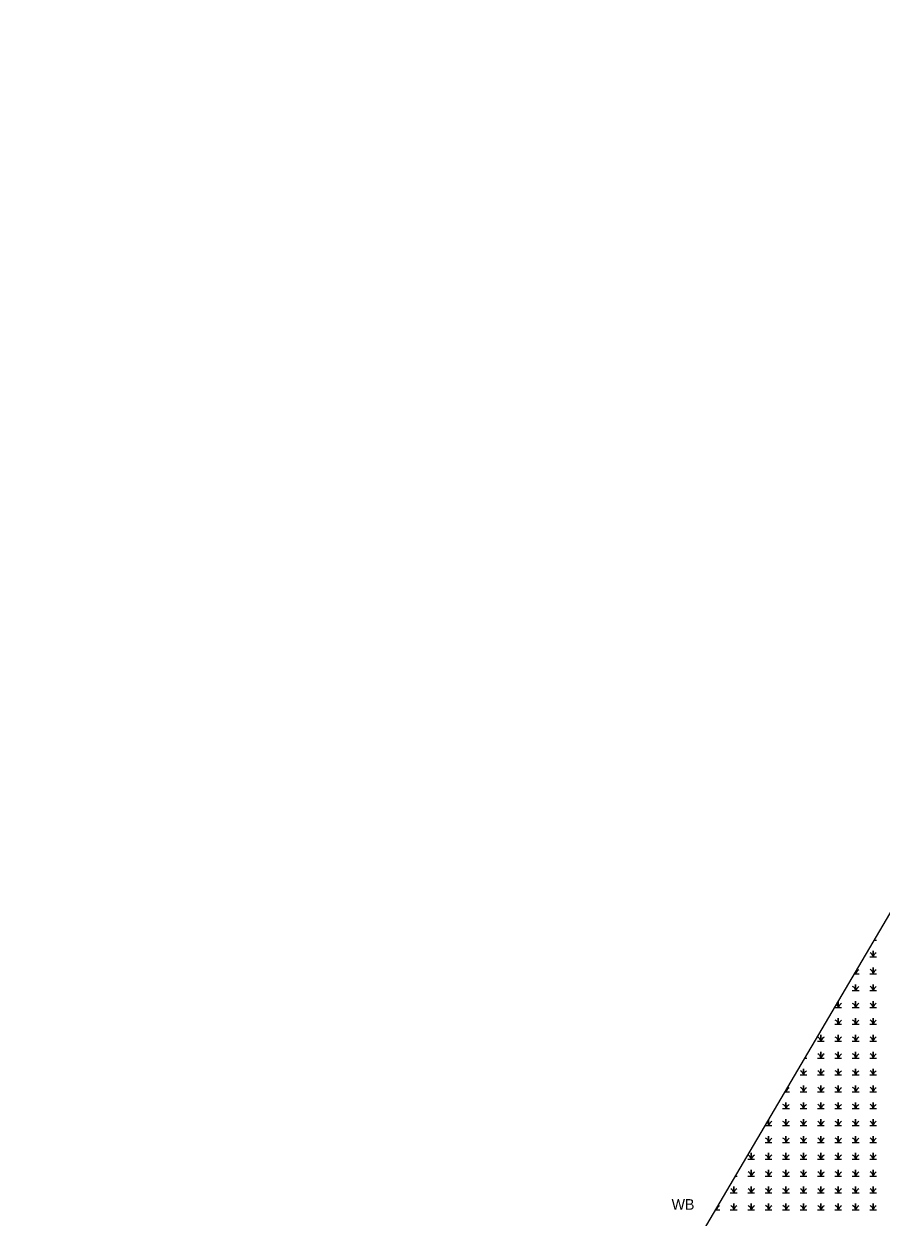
# Model space of a CAD drawing. Extents: x 2379288 to 2381905, y 330670 to 333511.
# Drawn here: x 2379288 to 2380098, y 331977 to 333104 of the extents above; entities that cross this region are included whole.
import ezdxf

# ---------------------------------------------------------------- set-up
doc = ezdxf.new("R2010")
doc.units = 0
for name, color, linetype in [('Default', 7, 'Continuous'), ('Exist Environmental Wetland Boundary Text', 7, 'Continuous'), ('Exist Hydro Swamp or Marsh', 7, 'Continuous')]:
    doc.layers.add(name, color=color, linetype=linetype)

msp = doc.modelspace()

# ---------------------------------------------------------------- linework, layer by layer
at = {"layer": 'Default'}
msp.add_lwpolyline([(2379288.1, 330873.4), (2380109.3, 332268.6), (2380147.9, 332331.8), (2380190.7, 332397.5), (2380235.6, 332461.8), (2380282.6, 332524.7), (2380331.5, 332586), (2380382.3, 332645.8), (2380434.9, 332703.9), (2380489.4, 332760.3), (2380545.6, 332815), (2380603.5, 332867.9), (2380663.1, 332919), (2380724.2, 332968.1), (2380786.8, 333015.3), (2380851, 333060.5), (2380916.5, 333103.7)], dxfattribs=at)
at = {"layer": 'Exist Hydro Swamp or Marsh'}
for p, q in [((2380091.8, 332238.4), (2380093.5, 332238.4)), ((2380026, 332127), (2380027.7, 332127)), ((2379960.4, 332015.6), (2379961.9, 332015.6))]:
    msp.add_line(p, q, dxfattribs=at)
for points in [[(2380087.1, 332222.5), (2380090.3, 332222.5), (2380090.3, 332228.4), (2380090.3, 332222.5), (2380093.5, 332222.5)], [(2380072.9, 332206.6), (2380073.8, 332206.6), (2380073.8, 332208.1)], [(2380073.8, 332208.1), (2380073.8, 332206.6), (2380077.1, 332206.6)], [(2380087.1, 332206.6), (2380090.3, 332206.6), (2380090.3, 332212.5), (2380090.3, 332206.6), (2380093.5, 332206.6)], [(2380070.6, 332190.7), (2380073.8, 332190.7), (2380073.8, 332196.6), (2380073.8, 332190.7), (2380077.1, 332190.7)], [(2380087.1, 332190.7), (2380090.3, 332190.7), (2380090.3, 332196.6), (2380090.3, 332190.7), (2380093.5, 332190.7)], [(2380054.2, 332174.8), (2380057.4, 332174.8), (2380057.4, 332180.4)], [(2380057.4, 332180.4), (2380057.4, 332174.8), (2380060.6, 332174.8)], [(2380070.6, 332174.8), (2380073.8, 332174.8), (2380073.8, 332180.7), (2380073.8, 332174.8), (2380077.1, 332174.8)], [(2380087.1, 332174.8), (2380090.3, 332174.8), (2380090.3, 332180.7), (2380090.3, 332174.8), (2380093.5, 332174.8)], [(2380054.2, 332158.9), (2380057.4, 332158.9), (2380057.4, 332164.8), (2380057.4, 332158.9), (2380060.6, 332158.9)], [(2380070.6, 332158.9), (2380073.8, 332158.9), (2380073.8, 332164.8), (2380073.8, 332158.9), (2380077.1, 332158.9)], [(2380087.1, 332158.9), (2380090.3, 332158.9), (2380090.3, 332164.8), (2380090.3, 332158.9), (2380093.5, 332158.9)], [(2380037.7, 332142.9), (2380040.9, 332142.9), (2380040.9, 332148.9), (2380040.9, 332142.9), (2380044.2, 332142.9)], [(2380054.2, 332142.9), (2380057.4, 332142.9), (2380057.4, 332148.9), (2380057.4, 332142.9), (2380060.6, 332142.9)], [(2380070.6, 332142.9), (2380073.8, 332142.9), (2380073.8, 332148.9), (2380073.8, 332142.9), (2380077.1, 332142.9)], [(2380087.1, 332142.9), (2380090.3, 332142.9), (2380090.3, 332148.9), (2380090.3, 332142.9), (2380093.5, 332142.9)], [(2380037.7, 332127), (2380040.9, 332127), (2380040.9, 332132.9), (2380040.9, 332127), (2380044.2, 332127)], [(2380054.2, 332127), (2380057.4, 332127), (2380057.4, 332132.9), (2380057.4, 332127), (2380060.6, 332127)], [(2380070.6, 332127), (2380073.8, 332127), (2380073.8, 332132.9), (2380073.8, 332127), (2380077.1, 332127)], [(2380087.1, 332127), (2380090.3, 332127), (2380090.3, 332132.9), (2380090.3, 332127), (2380093.5, 332127)], [(2380021.3, 332111.1), (2380024.5, 332111.1), (2380024.5, 332117), (2380024.5, 332111.1), (2380027.7, 332111.1)], [(2380037.7, 332111.1), (2380040.9, 332111.1), (2380040.9, 332117), (2380040.9, 332111.1), (2380044.2, 332111.1)], [(2380054.2, 332111.1), (2380057.4, 332111.1), (2380057.4, 332117), (2380057.4, 332111.1), (2380060.6, 332111.1)], [(2380070.6, 332111.1), (2380073.8, 332111.1), (2380073.8, 332117), (2380073.8, 332111.1), (2380077.1, 332111.1)], [(2380087.1, 332111.1), (2380090.3, 332111.1), (2380090.3, 332117), (2380090.3, 332111.1), (2380093.5, 332111.1)], [(2380007.2, 332095.2), (2380008, 332095.2), (2380008, 332096.5)], [(2380008, 332096.5), (2380008, 332095.2), (2380011.3, 332095.2)], [(2380021.3, 332095.2), (2380024.5, 332095.2), (2380024.5, 332101.1), (2380024.5, 332095.2), (2380027.7, 332095.2)], [(2380037.7, 332095.2), (2380040.9, 332095.2), (2380040.9, 332101.1), (2380040.9, 332095.2), (2380044.2, 332095.2)], [(2380054.2, 332095.2), (2380057.4, 332095.2), (2380057.4, 332101.1), (2380057.4, 332095.2), (2380060.6, 332095.2)], [(2380070.6, 332095.2), (2380073.8, 332095.2), (2380073.8, 332101.1), (2380073.8, 332095.2), (2380077.1, 332095.2)], [(2380087.1, 332095.2), (2380090.3, 332095.2), (2380090.3, 332101.1), (2380090.3, 332095.2), (2380093.5, 332095.2)], [(2380004.8, 332079.3), (2380008, 332079.3), (2380008, 332085.2), (2380008, 332079.3), (2380011.3, 332079.3)], [(2380021.3, 332079.3), (2380024.5, 332079.3), (2380024.5, 332085.2), (2380024.5, 332079.3), (2380027.7, 332079.3)], [(2380037.7, 332079.3), (2380040.9, 332079.3), (2380040.9, 332085.2), (2380040.9, 332079.3), (2380044.2, 332079.3)], [(2380054.2, 332079.3), (2380057.4, 332079.3), (2380057.4, 332085.2), (2380057.4, 332079.3), (2380060.6, 332079.3)], [(2380070.6, 332079.3), (2380073.8, 332079.3), (2380073.8, 332085.2), (2380073.8, 332079.3), (2380077.1, 332079.3)], [(2380087.1, 332079.3), (2380090.3, 332079.3), (2380090.3, 332085.2), (2380090.3, 332079.3), (2380093.5, 332079.3)], [(2380004.8, 332063.4), (2380008, 332063.4), (2380008, 332069.3), (2380008, 332063.4), (2380011.3, 332063.4)], [(2380021.3, 332063.4), (2380024.5, 332063.4), (2380024.5, 332069.3), (2380024.5, 332063.4), (2380027.7, 332063.4)], [(2380037.7, 332063.4), (2380040.9, 332063.4), (2380040.9, 332069.3), (2380040.9, 332063.4), (2380044.2, 332063.4)], [(2380054.2, 332063.4), (2380057.4, 332063.4), (2380057.4, 332069.3), (2380057.4, 332063.4), (2380060.6, 332063.4)], [(2380070.6, 332063.4), (2380073.8, 332063.4), (2380073.8, 332069.3), (2380073.8, 332063.4), (2380077.1, 332063.4)], [(2380087.1, 332063.4), (2380090.3, 332063.4), (2380090.3, 332069.3), (2380090.3, 332063.4), (2380093.5, 332063.4)], [(2379988.5, 332063.4), (2379991.6, 332063.4), (2379991.6, 332068.6)], [(2379991.6, 332068.6), (2379991.6, 332063.4), (2379994.8, 332063.4)], [(2379988.3, 332047.4), (2379991.6, 332047.4), (2379991.6, 332053.4), (2379991.6, 332047.4), (2379994.8, 332047.4)], [(2380004.8, 332047.4), (2380008, 332047.4), (2380008, 332053.4), (2380008, 332047.4), (2380011.3, 332047.4)], [(2380021.3, 332047.4), (2380024.5, 332047.4), (2380024.5, 332053.4), (2380024.5, 332047.4), (2380027.7, 332047.4)], [(2380037.7, 332047.4), (2380040.9, 332047.4), (2380040.9, 332053.4), (2380040.9, 332047.4), (2380044.2, 332047.4)], [(2380054.2, 332047.4), (2380057.4, 332047.4), (2380057.4, 332053.4), (2380057.4, 332047.4), (2380060.6, 332047.4)], [(2380070.6, 332047.4), (2380073.8, 332047.4), (2380073.8, 332053.4), (2380073.8, 332047.4), (2380077.1, 332047.4)], [(2380087.1, 332047.4), (2380090.3, 332047.4), (2380090.3, 332053.4), (2380090.3, 332047.4), (2380093.5, 332047.4)], [(2379971.9, 332031.5), (2379975.1, 332031.5), (2379975.1, 332037.4), (2379975.1, 332031.5), (2379978.3, 332031.5)], [(2379988.3, 332031.5), (2379991.6, 332031.5), (2379991.6, 332037.4), (2379991.6, 332031.5), (2379994.8, 332031.5)], [(2380004.8, 332031.5), (2380008, 332031.5), (2380008, 332037.4), (2380008, 332031.5), (2380011.3, 332031.5)], [(2380021.3, 332031.5), (2380024.5, 332031.5), (2380024.5, 332037.4), (2380024.5, 332031.5), (2380027.7, 332031.5)], [(2380037.7, 332031.5), (2380040.9, 332031.5), (2380040.9, 332037.4), (2380040.9, 332031.5), (2380044.2, 332031.5)], [(2380054.2, 332031.5), (2380057.4, 332031.5), (2380057.4, 332037.4), (2380057.4, 332031.5), (2380060.6, 332031.5)], [(2380070.6, 332031.5), (2380073.8, 332031.5), (2380073.8, 332037.4), (2380073.8, 332031.5), (2380077.1, 332031.5)], [(2380087.1, 332031.5), (2380090.3, 332031.5), (2380090.3, 332037.4), (2380090.3, 332031.5), (2380093.5, 332031.5)], [(2379971.9, 332015.6), (2379975.1, 332015.6), (2379975.1, 332021.5), (2379975.1, 332015.6), (2379978.3, 332015.6)], [(2379988.3, 332015.6), (2379991.6, 332015.6), (2379991.6, 332021.5), (2379991.6, 332015.6), (2379994.8, 332015.6)], [(2380004.8, 332015.6), (2380008, 332015.6), (2380008, 332021.5), (2380008, 332015.6), (2380011.3, 332015.6)], [(2380021.3, 332015.6), (2380024.5, 332015.6), (2380024.5, 332021.5), (2380024.5, 332015.6), (2380027.7, 332015.6)], [(2380037.7, 332015.6), (2380040.9, 332015.6), (2380040.9, 332021.5), (2380040.9, 332015.6), (2380044.2, 332015.6)], [(2380054.2, 332015.6), (2380057.4, 332015.6), (2380057.4, 332021.5), (2380057.4, 332015.6), (2380060.6, 332015.6)], [(2380070.6, 332015.6), (2380073.8, 332015.6), (2380073.8, 332021.5), (2380073.8, 332015.6), (2380077.1, 332015.6)], [(2380087.1, 332015.6), (2380090.3, 332015.6), (2380090.3, 332021.5), (2380090.3, 332015.6), (2380093.5, 332015.6)], [(2379955.4, 331999.7), (2379958.7, 331999.7), (2379958.7, 332005.6), (2379958.7, 331999.7), (2379961.9, 331999.7)], [(2379971.9, 331999.7), (2379975.1, 331999.7), (2379975.1, 332005.6), (2379975.1, 331999.7), (2379978.3, 331999.7)], [(2379988.3, 331999.7), (2379991.6, 331999.7), (2379991.6, 332005.6), (2379991.6, 331999.7), (2379994.8, 331999.7)], [(2380004.8, 331999.7), (2380008, 331999.7), (2380008, 332005.6), (2380008, 331999.7), (2380011.3, 331999.7)], [(2380021.3, 331999.7), (2380024.5, 331999.7), (2380024.5, 332005.6), (2380024.5, 331999.7), (2380027.7, 331999.7)], [(2380037.7, 331999.7), (2380040.9, 331999.7), (2380040.9, 332005.6), (2380040.9, 331999.7), (2380044.2, 331999.7)], [(2380054.2, 331999.7), (2380057.4, 331999.7), (2380057.4, 332005.6), (2380057.4, 331999.7), (2380060.6, 331999.7)], [(2380070.6, 331999.7), (2380073.8, 331999.7), (2380073.8, 332005.6), (2380073.8, 331999.7), (2380077.1, 331999.7)], [(2380087.1, 331999.7), (2380090.3, 331999.7), (2380090.3, 332005.6), (2380090.3, 331999.7), (2380093.5, 331999.7)], [(2379941.7, 331983.8), (2379942.2, 331983.8), (2379942.2, 331984.7)], [(2379942.2, 331984.7), (2379942.2, 331983.8), (2379945.4, 331983.8)], [(2379955.4, 331983.8), (2379958.7, 331983.8), (2379958.7, 331989.7), (2379958.7, 331983.8), (2379961.9, 331983.8)], [(2379971.9, 331983.8), (2379975.1, 331983.8), (2379975.1, 331989.7), (2379975.1, 331983.8), (2379978.3, 331983.8)], [(2379988.3, 331983.8), (2379991.6, 331983.8), (2379991.6, 331989.7), (2379991.6, 331983.8), (2379994.8, 331983.8)], [(2380004.8, 331983.8), (2380008, 331983.8), (2380008, 331989.7), (2380008, 331983.8), (2380011.3, 331983.8)], [(2380021.3, 331983.8), (2380024.5, 331983.8), (2380024.5, 331989.7), (2380024.5, 331983.8), (2380027.7, 331983.8)], [(2380037.7, 331983.8), (2380040.9, 331983.8), (2380040.9, 331989.7), (2380040.9, 331983.8), (2380044.2, 331983.8)], [(2380054.2, 331983.8), (2380057.4, 331983.8), (2380057.4, 331989.7), (2380057.4, 331983.8), (2380060.6, 331983.8)], [(2380070.6, 331983.8), (2380073.8, 331983.8), (2380073.8, 331989.7), (2380073.8, 331983.8), (2380077.1, 331983.8)], [(2380087.1, 331983.8), (2380090.3, 331983.8), (2380090.3, 331989.7), (2380090.3, 331983.8), (2380093.5, 331983.8)]]:
    msp.add_lwpolyline(points, dxfattribs=at)
for centre, radius, start, end in [((2380085.7, 332222.2), 4.61, 4.1403, 67.535), ((2380097.1, 332220.3), 7.21, 122.1274, 161.6222), ((2380069.2, 332206.3), 4.61, 4.1403, 18.2723), ((2380080.7, 332204.3), 7.21, 122.1274, 161.6222), ((2380085.7, 332206.3), 4.61, 4.1403, 67.535), ((2380097.1, 332204.3), 7.21, 122.1274, 161.6222), ((2380069.2, 332190.4), 4.61, 4.1403, 67.535), ((2380080.7, 332188.4), 7.21, 122.1274, 161.6222), ((2380085.7, 332190.4), 4.61, 4.1403, 67.535), ((2380097.1, 332188.4), 7.21, 122.1274, 161.6222), ((2380052.8, 332174.4), 4.61, 4.1403, 47.5604), ((2380064.2, 332172.5), 7.21, 122.1274, 161.6222), ((2380069.2, 332174.4), 4.61, 4.1403, 67.535), ((2380080.7, 332172.5), 7.21, 122.1274, 161.6222), ((2380085.7, 332174.4), 4.61, 4.1403, 67.535), ((2380097.1, 332172.5), 7.21, 122.1274, 161.6222), ((2380052.8, 332158.5), 4.61, 4.1403, 67.535), ((2380064.2, 332156.6), 7.21, 122.1274, 161.6222), ((2380069.2, 332158.5), 4.61, 4.1403, 67.535), ((2380080.7, 332156.6), 7.21, 122.1274, 161.6222), ((2380085.7, 332158.5), 4.61, 4.1403, 67.535), ((2380097.1, 332156.6), 7.21, 122.1274, 161.6222), ((2380036.3, 332142.6), 4.61, 4.1403, 67.535), ((2380047.8, 332140.7), 7.21, 122.1274, 161.6222), ((2380052.8, 332142.6), 4.61, 4.1403, 67.535), ((2380064.2, 332140.7), 7.21, 122.1274, 161.6222), ((2380069.2, 332142.6), 4.61, 4.1403, 67.535), ((2380080.7, 332140.7), 7.21, 122.1274, 161.6222), ((2380085.7, 332142.6), 4.61, 4.1403, 67.535), ((2380097.1, 332140.7), 7.21, 122.1274, 161.6222), ((2380036.3, 332126.7), 4.61, 4.1403, 67.535), ((2380047.8, 332124.8), 7.21, 122.1274, 161.6222), ((2380052.8, 332126.7), 4.61, 4.1403, 67.535), ((2380064.2, 332124.8), 7.21, 122.1274, 161.6222), ((2380069.2, 332126.7), 4.61, 4.1403, 67.535), ((2380080.7, 332124.8), 7.21, 122.1274, 161.6222), ((2380085.7, 332126.7), 4.61, 4.1403, 67.535), ((2380097.1, 332124.8), 7.21, 122.1274, 161.6222), ((2380019.9, 332110.8), 4.61, 4.1403, 67.535), ((2380031.3, 332108.8), 7.21, 122.1274, 161.6222), ((2380036.3, 332110.8), 4.61, 4.1403, 67.535), ((2380047.8, 332108.8), 7.21, 122.1274, 161.6222), ((2380052.8, 332110.8), 4.61, 4.1403, 67.535), ((2380064.2, 332108.8), 7.21, 122.1274, 161.6222), ((2380069.2, 332110.8), 4.61, 4.1403, 67.535), ((2380080.7, 332108.8), 7.21, 122.1274, 161.6222), ((2380085.7, 332110.8), 4.61, 4.1403, 67.535), ((2380097.1, 332108.8), 7.21, 122.1274, 161.6222), ((2380003.4, 332094.9), 4.61, 4.1403, 17.0082), ((2380014.9, 332092.9), 7.21, 122.1274, 161.6222), ((2380019.9, 332094.9), 4.61, 4.1403, 67.535), ((2380031.3, 332092.9), 7.21, 122.1274, 161.6222), ((2380036.3, 332094.9), 4.61, 4.1403, 67.535), ((2380047.8, 332092.9), 7.21, 122.1274, 161.6222), ((2380052.8, 332094.9), 4.61, 4.1403, 67.535), ((2380064.2, 332092.9), 7.21, 122.1274, 161.6222), ((2380069.2, 332094.9), 4.61, 4.1403, 67.535), ((2380080.7, 332092.9), 7.21, 122.1274, 161.6222), ((2380085.7, 332094.9), 4.61, 4.1403, 67.535), ((2380097.1, 332092.9), 7.21, 122.1274, 161.6222), ((2380003.4, 332078.9), 4.61, 4.1403, 67.535), ((2380014.9, 332077), 7.21, 122.1274, 161.6222), ((2380019.9, 332078.9), 4.61, 4.1403, 67.535), ((2380031.3, 332077), 7.21, 122.1274, 161.6222), ((2380036.3, 332078.9), 4.61, 4.1403, 67.535), ((2380047.8, 332077), 7.21, 122.1274, 161.6222), ((2380052.8, 332078.9), 4.61, 4.1403, 67.535), ((2380064.2, 332077), 7.21, 122.1274, 161.6222), ((2380069.2, 332078.9), 4.61, 4.1403, 67.535), ((2380080.7, 332077), 7.21, 122.1274, 161.6222), ((2380085.7, 332078.9), 4.61, 4.1403, 67.535), ((2380097.1, 332077), 7.21, 122.1274, 161.6222), ((2379987, 332063), 4.61, 4.1403, 45.1411), ((2379998.4, 332061.1), 7.21, 122.1274, 161.6222), ((2380003.4, 332063), 4.61, 4.1403, 67.535), ((2380014.9, 332061.1), 7.21, 122.1274, 161.6222), ((2380019.9, 332063), 4.61, 4.1403, 67.535), ((2380031.3, 332061.1), 7.21, 122.1274, 161.6222), ((2380036.3, 332063), 4.61, 4.1403, 67.535), ((2380047.8, 332061.1), 7.21, 122.1274, 161.6222), ((2380052.8, 332063), 4.61, 4.1403, 67.535), ((2380064.2, 332061.1), 7.21, 122.1274, 161.6222), ((2380069.2, 332063), 4.61, 4.1403, 67.535), ((2380080.7, 332061.1), 7.21, 122.1274, 161.6222), ((2380085.7, 332063), 4.61, 4.1403, 67.535), ((2380097.1, 332061.1), 7.21, 122.1274, 161.6222), ((2379987, 332047.1), 4.61, 4.1403, 67.535), ((2379998.4, 332045.2), 7.21, 122.1274, 161.6222), ((2380003.4, 332047.1), 4.61, 4.1403, 67.535), ((2380014.9, 332045.2), 7.21, 122.1274, 161.6222), ((2380019.9, 332047.1), 4.61, 4.1403, 67.535), ((2380031.3, 332045.2), 7.21, 122.1274, 161.6222), ((2380036.3, 332047.1), 4.61, 4.1403, 67.535), ((2380047.8, 332045.2), 7.21, 122.1274, 161.6222), ((2380052.8, 332047.1), 4.61, 4.1403, 67.535), ((2380064.2, 332045.2), 7.21, 122.1274, 161.6222), ((2380069.2, 332047.1), 4.61, 4.1403, 67.535), ((2380080.7, 332045.2), 7.21, 122.1274, 161.6222), ((2380085.7, 332047.1), 4.61, 4.1403, 67.535), ((2380097.1, 332045.2), 7.21, 122.1274, 161.6222), ((2379970.5, 332031.2), 4.61, 4.1403, 67.535), ((2379982, 332029.2), 7.21, 122.1274, 161.6222), ((2379987, 332031.2), 4.61, 4.1403, 67.535), ((2379998.4, 332029.2), 7.21, 122.1274, 161.6222), ((2380003.4, 332031.2), 4.61, 4.1403, 67.535), ((2380014.9, 332029.2), 7.21, 122.1274, 161.6222), ((2380019.9, 332031.2), 4.61, 4.1403, 67.535), ((2380031.3, 332029.2), 7.21, 122.1274, 161.6222), ((2380036.3, 332031.2), 4.61, 4.1403, 67.535), ((2380047.8, 332029.2), 7.21, 122.1274, 161.6222), ((2380052.8, 332031.2), 4.61, 4.1403, 67.535), ((2380064.2, 332029.2), 7.21, 122.1274, 161.6222), ((2380069.2, 332031.2), 4.61, 4.1403, 67.535), ((2380080.7, 332029.2), 7.21, 122.1274, 161.6222), ((2380085.7, 332031.2), 4.61, 4.1403, 67.535), ((2380097.1, 332029.2), 7.21, 122.1274, 161.6222), ((2379970.5, 332015.3), 4.61, 4.1403, 67.535), ((2379982, 332013.3), 7.21, 122.1274, 161.6222), ((2379987, 332015.3), 4.61, 4.1403, 67.535), ((2379998.4, 332013.3), 7.21, 122.1274, 161.6222), ((2380003.4, 332015.3), 4.61, 4.1403, 67.535), ((2380014.9, 332013.3), 7.21, 122.1274, 161.6222), ((2380019.9, 332015.3), 4.61, 4.1403, 67.535), ((2380031.3, 332013.3), 7.21, 122.1274, 161.6222), ((2380036.3, 332015.3), 4.61, 4.1403, 67.535), ((2380047.8, 332013.3), 7.21, 122.1274, 161.6222), ((2380052.8, 332015.3), 4.61, 4.1403, 67.535), ((2380064.2, 332013.3), 7.21, 122.1274, 161.6222), ((2380069.2, 332015.3), 4.61, 4.1403, 67.535), ((2380080.7, 332013.3), 7.21, 122.1274, 161.6222), ((2380085.7, 332015.3), 4.61, 4.1403, 67.535), ((2380097.1, 332013.3), 7.21, 122.1274, 161.6222), ((2379954.1, 331999.3), 4.61, 4.1403, 67.535), ((2379965.5, 331997.4), 7.21, 122.1274, 161.6222), ((2379970.5, 331999.3), 4.61, 4.1403, 67.535), ((2379982, 331997.4), 7.21, 122.1274, 161.6222), ((2379987, 331999.3), 4.61, 4.1403, 67.535), ((2379998.4, 331997.4), 7.21, 122.1274, 161.6222), ((2380003.4, 331999.3), 4.61, 4.1403, 67.535), ((2380014.9, 331997.4), 7.21, 122.1274, 161.6222), ((2380019.9, 331999.3), 4.61, 4.1403, 67.535), ((2380031.3, 331997.4), 7.21, 122.1274, 161.6222), ((2380036.3, 331999.3), 4.61, 4.1403, 67.535), ((2380047.8, 331997.4), 7.21, 122.1274, 161.6222), ((2380052.8, 331999.3), 4.61, 4.1403, 67.535), ((2380064.2, 331997.4), 7.21, 122.1274, 161.6222), ((2380069.2, 331999.3), 4.61, 4.1403, 67.535), ((2380080.7, 331997.4), 7.21, 122.1274, 161.6222), ((2380085.7, 331999.3), 4.61, 4.1403, 67.535), ((2380097.1, 331997.4), 7.21, 122.1274, 161.6222), ((2379937.6, 331983.4), 4.61, 4.1403, 13.7246), ((2379949.1, 331981.5), 7.21, 122.1274, 161.6222), ((2379954.1, 331983.4), 4.61, 4.1403, 67.535), ((2379965.5, 331981.5), 7.21, 122.1274, 161.6222), ((2379970.5, 331983.4), 4.61, 4.1403, 67.535), ((2379982, 331981.5), 7.21, 122.1274, 161.6222), ((2379987, 331983.4), 4.61, 4.1403, 67.535), ((2379998.4, 331981.5), 7.21, 122.1274, 161.6222), ((2380003.4, 331983.4), 4.61, 4.1403, 67.535), ((2380014.9, 331981.5), 7.21, 122.1274, 161.6222), ((2380019.9, 331983.4), 4.61, 4.1403, 67.535), ((2380031.3, 331981.5), 7.21, 122.1274, 161.6222), ((2380036.3, 331983.4), 4.61, 4.1403, 67.535), ((2380047.8, 331981.5), 7.21, 122.1274, 161.6222), ((2380052.8, 331983.4), 4.61, 4.1403, 67.535), ((2380064.2, 331981.5), 7.21, 122.1274, 161.6222), ((2380069.2, 331983.4), 4.61, 4.1403, 67.535), ((2380080.7, 331981.5), 7.21, 122.1274, 161.6222), ((2380085.7, 331983.4), 4.61, 4.1403, 67.535), ((2380097.1, 331981.5), 7.21, 122.1274, 161.6222)]:
    msp.add_arc(centre, radius, start, end, dxfattribs=at)

# ---------------------------------------------------------------- texts
at = {"layer": 'Exist Environmental Wetland Boundary Text'}
msp.add_text('WB', height=10, dxfattribs=at).set_placement((2379900, 331983.8))

doc.saveas('drawing.dxf')
